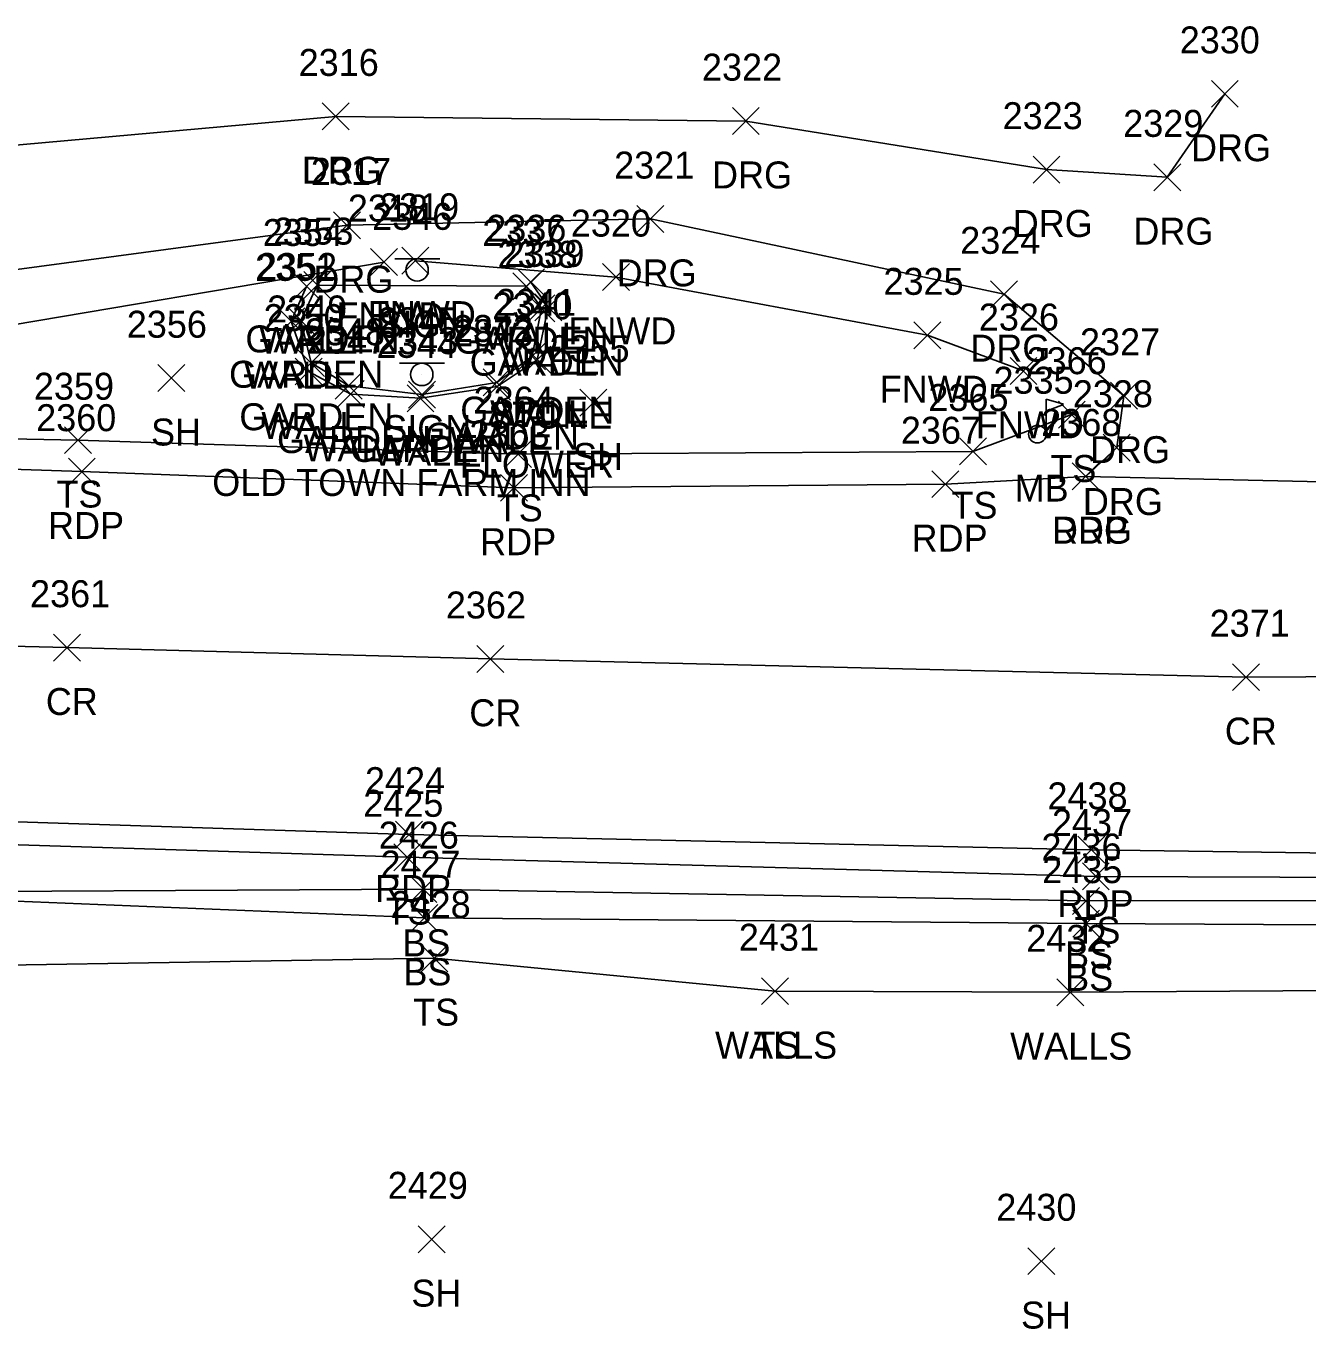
# Model space of a CAD drawing. Extents: x 1611797 to 1633212, y 298978 to 305475.
# Drawn here: x 1615253.5 to 1615348.7, y 301457.7 to 301554.4 of the extents above; entities that cross this region are included whole.
import ezdxf

# ---------------------------------------------------------------- set-up
doc = ezdxf.new("R2010")
doc.units = 0
for name, color, linetype in [('L_A', 7, 'Continuous'), ('L_C', 7, 'Continuous'), ('L_I', 7, 'Continuous'), ('L_TIC', 7, 'Continuous'), ('LAPB', 7, 'Continuous'), ('LELB', 7, 'Continuous'), ('LFNC', 7, 'Continuous'), ('LMB', 7, 'Continuous'), ('LW', 7, 'Continuous'), ('LWS', 7, 'Continuous'), ('P_A', 7, 'Continuous'), ('P_I', 7, 'Continuous'), ('P_TIC', 7, 'Continuous'), ('PET', 7, 'Continuous'), ('PRC', 7, 'Continuous'), ('R_A', 7, 'Continuous'), ('R_I', 7, 'Continuous'), ('R_TIC', 7, 'Continuous'), ('RDG', 7, 'Continuous'), ('S_A', 7, 'Continuous'), ('S_C', 7, 'Continuous'), ('S_I', 7, 'Continuous'), ('SSGN', 7, 'Continuous')]:
    doc.layers.add(name, color=color, linetype=linetype)

msp = doc.modelspace()

# ---------------------------------------------------------------- linework, layer by layer
at = {"layer": 'L_TIC'}
for points in [[(1615279.11, 301535.848), (1615281.11, 301537.848)], [(1615281.11, 301535.848), (1615279.11, 301537.848)], [(1615281.438, 301535.946), (1615283.438, 301537.946)], [(1615283.438, 301535.946), (1615281.438, 301537.946)], [(1615290.01, 301534.353), (1615292.01, 301536.353)], [(1615292.01, 301534.353), (1615290.01, 301536.353)], [(1615296.319, 301534.735), (1615298.319, 301536.735)], [(1615298.319, 301534.735), (1615296.319, 301536.735)], [(1615273.359, 301534.038), (1615275.359, 301536.038)], [(1615275.359, 301534.038), (1615273.359, 301536.038)], [(1615274.144, 301534.142), (1615276.144, 301536.142)], [(1615276.144, 301534.142), (1615274.144, 301536.142)], [(1615274.144, 301534.142), (1615276.144, 301536.142)], [(1615276.144, 301534.142), (1615274.144, 301536.142)], [(1615289.662, 301534.047), (1615291.662, 301536.047)], [(1615291.662, 301534.047), (1615289.662, 301536.047)], [(1615289.662, 301534.047), (1615291.662, 301536.047)], [(1615291.662, 301534.047), (1615289.662, 301536.047)], [(1615290.791, 301532.419), (1615292.791, 301534.419)], [(1615292.791, 301532.419), (1615290.791, 301534.419)], [(1615291.301, 301532.49), (1615293.301, 301534.49)], [(1615293.301, 301532.49), (1615291.301, 301534.49)], [(1615272.222, 301531.452), (1615274.222, 301533.452)], [(1615274.222, 301531.452), (1615272.222, 301533.452)], [(1615272.93, 301531.52), (1615274.93, 301533.52)], [(1615274.93, 301531.52), (1615272.93, 301533.52)], [(1615319.445, 301530.414), (1615321.445, 301532.414)], [(1615321.445, 301530.414), (1615319.445, 301532.414)], [(1615290.099, 301528.856), (1615292.099, 301530.856)], [(1615292.099, 301528.856), (1615290.099, 301530.856)], [(1615290.486, 301528.594), (1615292.486, 301530.594)], [(1615292.486, 301528.594), (1615290.486, 301530.594)], [(1615273.506, 301527.724), (1615275.506, 301529.724)], [(1615275.506, 301527.724), (1615273.506, 301529.724)], [(1615273.692, 301528.365), (1615275.692, 301530.365)], [(1615275.692, 301528.365), (1615273.692, 301530.365)], [(1615326.581, 301527.766), (1615328.581, 301529.766)], [(1615328.581, 301527.766), (1615326.581, 301529.766)], [(1615263.321, 301527.232), (1615265.321, 301529.232)], [(1615265.321, 301527.232), (1615263.321, 301529.232)], [(1615276.49, 301526.669), (1615278.49, 301528.669)], [(1615278.49, 301526.669), (1615276.49, 301528.669)], [(1615287.477, 301526.919), (1615289.477, 301528.919)], [(1615289.477, 301526.919), (1615287.477, 301528.919)], [(1615287.5, 301526.6), (1615289.5, 301528.6)], [(1615289.5, 301526.6), (1615287.5, 301528.6)], [(1615276.636, 301526.049), (1615278.636, 301528.049)], [(1615278.636, 301526.049), (1615276.636, 301528.049)], [(1615281.815, 301525.738), (1615283.815, 301527.738)], [(1615283.815, 301525.738), (1615281.815, 301527.738)], [(1615281.919, 301526.012), (1615283.919, 301528.012)], [(1615283.919, 301526.012), (1615281.919, 301528.012)], [(1615294.644, 301525.418), (1615296.644, 301527.418)], [(1615296.644, 301525.418), (1615294.644, 301527.418)], [(1615330.171, 301524.525), (1615332.171, 301526.525)], [(1615332.171, 301524.525), (1615330.171, 301526.525)], [(1615256.378, 301522.63), (1615258.378, 301524.63)], [(1615258.378, 301522.63), (1615256.378, 301524.63)], [(1615322.825, 301521.795), (1615324.825, 301523.795)], [(1615324.825, 301521.795), (1615322.825, 301523.795)], [(1615289.065, 301521.601), (1615291.065, 301523.601)], [(1615291.065, 301521.601), (1615289.065, 301523.601)], [(1615280.823, 301491.679), (1615282.823, 301493.679)], [(1615282.823, 301491.679), (1615280.823, 301493.679)], [(1615331.953, 301490.253), (1615333.953, 301492.253)], [(1615333.953, 301490.253), (1615331.953, 301492.253)], [(1615282.024, 301489.319), (1615284.024, 301491.319)], [(1615284.024, 301489.319), (1615282.024, 301491.319)], [(1615331.229, 301488.433), (1615333.229, 301490.433)], [(1615333.229, 301488.433), (1615331.229, 301490.433)], [(1615282.104, 301487.171), (1615284.104, 301489.171)], [(1615284.104, 301487.171), (1615282.104, 301489.171)], [(1615331.233, 301486.755), (1615333.233, 301488.755)], [(1615333.233, 301486.755), (1615331.233, 301488.755)], [(1615282.851, 301484.18), (1615284.851, 301486.18)], [(1615284.851, 301484.18), (1615282.851, 301486.18)], [(1615308.139, 301481.738), (1615310.139, 301483.738)], [(1615310.139, 301481.738), (1615308.139, 301483.738)], [(1615308.139, 301481.738), (1615310.139, 301483.738)], [(1615310.139, 301481.738), (1615308.139, 301483.738)], [(1615330.05, 301481.658), (1615332.05, 301483.658)], [(1615332.05, 301481.658), (1615330.05, 301483.658)], [(1615282.648, 301463.33), (1615284.648, 301465.33)], [(1615284.648, 301463.33), (1615282.648, 301465.33)], [(1615327.909, 301461.7), (1615329.909, 301463.7)], [(1615329.909, 301461.7), (1615327.909, 301463.7)]]:
    msp.add_lwpolyline(points, dxfattribs=at)
at = {"layer": 'LAPB'}
for points in [[(1615290.662, 301535.047), (1615291.791, 301533.419), (1615291.099, 301529.856), (1615288.477, 301527.919), (1615282.919, 301527.012), (1615277.49, 301527.669), (1615274.692, 301529.365), (1615273.93, 301532.52), (1615275.144, 301535.142)], [(1615290.662, 301535.047), (1615275.144, 301535.142)]]:
    msp.add_lwpolyline(points, dxfattribs=at)
at = {"layer": 'LELB'}
for points in [[(1615230.11, 301524.922), (1615238.425, 301524.007), (1615257.378, 301523.63), (1615290.065, 301522.601), (1615323.825, 301522.795), (1615331.171, 301525.525)], [(1615135.071, 301495.761), (1615182.71, 301493.095), (1615200.62, 301491.369), (1615237.017, 301490.049), (1615283.024, 301490.319), (1615332.229, 301489.433), (1615367.288, 301489.489), (1615415.165, 301489.476), (1615461.146, 301487.512), (1615489.04, 301481.907), (1615489.776, 301481.977), (1615494.762, 301481.706), (1615499.219, 301481.59), (1615505.435, 301481.232), (1615512.849, 301484.982), (1615523.287, 301488.148), (1615565.537, 301489.63)], [(1615179.356, 301495.542), (1615238.13, 301494.061), (1615281.823, 301492.679), (1615332.953, 301491.253), (1615367.08, 301491.116), (1615415.17, 301490.398), (1615463.455, 301489.366), (1615485.767, 301488.198), (1615488.262, 301485.173)], [(1615134.448, 301474.569), (1615137.467, 301487.518), (1615142.682, 301492.896), (1615182.793, 301490.04), (1615200.101, 301488.135), (1615232.281, 301484.351), (1615283.851, 301485.18), (1615309.139, 301482.738)], [(1615237.017, 301490.049), (1615283.104, 301488.171), (1615332.233, 301487.755), (1615367.345, 301487.55), (1615415.322, 301486.919), (1615460.207, 301484.871), (1615489.369, 301480.08), (1615494.635, 301473.717)]]:
    msp.add_lwpolyline(points, dxfattribs=at)
at = {"layer": 'LFNC'}
for points in [[(1615233.571, 301526.811), (1615248.741, 301531.535), (1615280.11, 301536.848)], [(1615282.438, 301536.946), (1615297.319, 301535.735), (1615320.445, 301531.414), (1615327.581, 301528.766)]]:
    msp.add_lwpolyline(points, dxfattribs=at)
at = {"layer": 'LMB'}
for p, q in [((1615329.261, 301526.676), (1615330.555, 301526.294)), ((1615329.268, 301524.083), (1615329.266, 301526.678)), ((1615329.266, 301525.776), (1615330.549, 301526.285)), ((1615328.612, 301524.075), (1615328.612, 301524.075))]:
    msp.add_line(p, q, dxfattribs=at)
msp.add_circle((1615328.611, 301524.075), 0.656, dxfattribs=at)
at = {"layer": 'LW'}
msp.add_lwpolyline([(1615291.01, 301535.353), (1615292.301, 301533.49), (1615291.486, 301529.594), (1615288.5, 301527.6), (1615282.815, 301526.738), (1615277.636, 301527.049), (1615274.506, 301528.724), (1615273.222, 301532.452), (1615274.359, 301535.038)], dxfattribs=at)
at = {"layer": 'LWS'}
msp.add_lwpolyline([(1615309.139, 301482.738), (1615331.05, 301482.658), (1615358.695, 301482.848), (1615417.126, 301482.013), (1615442.972, 301482.142), (1615457.095, 301482.675), (1615467.781, 301481.999)], dxfattribs=at)
at = {"layer": 'P_TIC'}
for points in [[(1615256.671, 301520.297), (1615258.671, 301522.297)], [(1615258.671, 301520.297), (1615256.671, 301522.297)], [(1615331.204, 301519.943), (1615333.204, 301521.943)], [(1615333.204, 301519.943), (1615331.204, 301521.943)], [(1615288.753, 301519.093), (1615290.753, 301521.093)], [(1615290.753, 301519.093), (1615288.753, 301521.093)], [(1615320.783, 301519.363), (1615322.783, 301521.363)], [(1615322.783, 301519.363), (1615320.783, 301521.363)], [(1615255.563, 301507.234), (1615257.563, 301509.234)], [(1615257.563, 301507.234), (1615255.563, 301509.234)], [(1615287.003, 301506.397), (1615289.003, 301508.397)], [(1615289.003, 301506.397), (1615287.003, 301508.397)], [(1615343.096, 301505.041), (1615345.096, 301507.041)], [(1615345.096, 301505.041), (1615343.096, 301507.041)], [(1615280.951, 301493.361), (1615282.951, 301495.361)], [(1615282.951, 301493.361), (1615280.951, 301495.361)], [(1615331.62, 301492.231), (1615333.62, 301494.231)], [(1615333.62, 301492.231), (1615331.62, 301494.231)]]:
    msp.add_lwpolyline(points, dxfattribs=at)
at = {"layer": 'PET'}
for points in [[(1615142.946, 301524.074), (1615174.411, 301524.044), (1615178.387, 301526.37), (1615201.604, 301526.436), (1615223.594, 301525.799), (1615232.103, 301522.147), (1615257.671, 301521.297), (1615289.753, 301520.093), (1615321.783, 301520.363), (1615332.204, 301520.943), (1615362.893, 301520.238), (1615366.82, 301519.177), (1615392.251, 301518.728), (1615435.41, 301518.321), (1615495.64, 301517.787), (1615533.402, 301517.836), (1615565.945, 301517.336)], [(1615136.457, 301498.095), (1615183.514, 301496.737), (1615238.286, 301495.772), (1615281.951, 301494.361), (1615332.62, 301493.231), (1615366.847, 301492.766), (1615415.142, 301492.226), (1615463.728, 301491.907), (1615523.213, 301491.769), (1615565.652, 301491.507), (1615604.418, 301491.288), (1615650.576, 301491.377), (1615696.82, 301491.212), (1615742.604, 301491.137), (1615790.502, 301490.828), (1615833.333, 301490.511), (1615872.315, 301490.361), (1615916.91, 301490.766), (1615952.964, 301490.824), (1615957.121, 301489.367), (1615991.141, 301489.805)]]:
    msp.add_lwpolyline(points, dxfattribs=at)
at = {"layer": 'PRC'}
msp.add_lwpolyline([(1615142.895, 301510.745), (1615196.64, 301509.677), (1615256.563, 301508.234), (1615288.003, 301507.397), (1615344.096, 301506.041), (1615366.393, 301506.163), (1615392.516, 301505.723), (1615432.008, 301505.199), (1615494.472, 301504.952), (1615533.598, 301504.748), (1615565.585, 301504.325), (1615604.181, 301504.079), (1615650.059, 301504.113), (1615697.506, 301503.8), (1615741.702, 301503.326), (1615791.714, 301502.936), (1615833.167, 301502.789), (1615874.42, 301502.642), (1615915.553, 301503.017), (1616010.706, 301505.129)], dxfattribs=at)
at = {"layer": 'R_TIC'}
for points in [[(1615341.529, 301548.33), (1615343.529, 301550.33)], [(1615343.529, 301548.33), (1615341.529, 301550.33)], [(1615275.517, 301546.66), (1615277.517, 301548.66)], [(1615277.517, 301546.66), (1615275.517, 301548.66)], [(1615305.969, 301546.31), (1615307.969, 301548.31)], [(1615307.969, 301546.31), (1615305.969, 301548.31)], [(1615328.292, 301542.709), (1615330.292, 301544.709)], [(1615330.292, 301542.709), (1615328.292, 301544.709)], [(1615337.252, 301542.137), (1615339.252, 301544.137)], [(1615339.252, 301542.137), (1615337.252, 301544.137)], [(1615298.883, 301539.043), (1615300.883, 301541.043)], [(1615300.883, 301539.043), (1615298.883, 301541.043)], [(1615276.365, 301538.573), (1615278.365, 301540.573)], [(1615278.365, 301538.573), (1615276.365, 301540.573)], [(1615325.142, 301533.458), (1615327.142, 301535.458)], [(1615327.142, 301533.458), (1615325.142, 301535.458)], [(1615334.036, 301525.924), (1615336.036, 301527.924)], [(1615336.036, 301525.924), (1615334.036, 301527.924)], [(1615333.502, 301522.074), (1615335.502, 301524.074)], [(1615335.502, 301522.074), (1615333.502, 301524.074)], [(1615331.204, 301519.943), (1615333.204, 301521.943)], [(1615333.204, 301519.943), (1615331.204, 301521.943)]]:
    msp.add_lwpolyline(points, dxfattribs=at)
at = {"layer": 'RDG'}
for points in [[(1615225.348, 301550.196), (1615232.765, 301544.839), (1615249.69, 301545.258), (1615276.517, 301547.66), (1615306.969, 301547.31), (1615329.292, 301543.709), (1615338.252, 301543.137), (1615342.529, 301549.33)], [(1615223.594, 301525.799), (1615227.571, 301529.431), (1615234.29, 301532.371), (1615248.754, 301535.742), (1615277.365, 301539.573), (1615299.883, 301540.043), (1615326.142, 301534.458), (1615335.036, 301526.924), (1615334.502, 301523.074), (1615332.204, 301520.943)]]:
    msp.add_lwpolyline(points, dxfattribs=at)
at = {"layer": 'SSGN'}
for p, q in [((1615280.913, 301537.091), (1615284.246, 301537.091)), ((1615282.56, 301536.258), (1615282.56, 301536.258)), ((1615281.26, 301529.341), (1615284.593, 301529.341)), ((1615282.907, 301528.508), (1615282.907, 301528.508))]:
    msp.add_line(p, q, dxfattribs=at)
for centre in [(1615282.56, 301536.258), (1615282.907, 301528.508)]:
    msp.add_circle(centre, 0.833, dxfattribs=at)

# ---------------------------------------------------------------- texts
at = {"layer": 'L_A'}
for s, p in [('FNWD', (1615276.575, 301531.848)), ('FNWD', (1615278.903, 301531.946)), ('WALL', (1615287.499, 301530.353)), ('FNWD', (1615293.784, 301530.735)), ('GARDEN', (1615269.814, 301530.142)), ('GARDEN', (1615269.814, 301530.142)), ('WALL', (1615270.847, 301530.038)), ('GARDEN', (1615285.332, 301530.047)), ('GARDEN', (1615285.332, 301530.047)), ('GARDEN', (1615286.461, 301528.419)), ('WALL', (1615288.79, 301528.49)), ('GARDEN', (1615268.6, 301527.52)), ('WALL', (1615269.71, 301527.452)), ('FNWD', (1615316.909, 301526.414)), ('GARDEN', (1615285.768, 301524.856)), ('WALL', (1615287.974, 301524.594)), ('GARDEN', (1615269.361, 301524.365)), ('WALL', (1615270.994, 301523.724)), ('FNWD', (1615324.046, 301523.766)), ('SH', (1615262.809, 301523.232)), ('GARDEN', (1615272.159, 301522.669)), ('GARDEN', (1615283.146, 301522.919)), ('WALL', (1615284.988, 301522.6)), ('WALL', (1615274.124, 301522.049)), ('GARDEN', (1615277.589, 301522.012)), ('WALL', (1615279.303, 301521.738)), ('SH', (1615294.132, 301521.418)), ('TS', (1615329.58, 301520.525)), ('MB', (1615326.919, 301519.075)), ('TS', (1615255.787, 301518.63)), ('TS', (1615322.234, 301517.795)), ('TS', (1615288.475, 301517.601)), ('TS', (1615280.232, 301487.679)), ('TS', (1615331.362, 301486.253)), ('BS', (1615281.465, 301485.319)), ('BS', (1615330.67, 301484.433)), ('BS', (1615281.545, 301483.171)), ('BS', (1615330.674, 301482.755)), ('TS', (1615282.26, 301480.18)), ('WALLS', (1615304.682, 301477.738)), ('TS', (1615307.548, 301477.738)), ('WALLS', (1615326.593, 301477.658)), ('SH', (1615282.136, 301459.33)), ('SH', (1615327.397, 301457.7))]:
    msp.add_text(s, height=2, dxfattribs=at).set_placement(p)
at = {"layer": 'L_C'}
for s, p in [('STONE', (1615287.845, 301524.49)), ('FLOWER', (1615285.737, 301520.856))]:
    msp.add_text(s, height=2, dxfattribs=at).set_placement(p)
at = {"layer": 'L_I'}
for s, p in [('2318', (1615277.418, 301539.848)), ('2319', (1615279.737, 301539.946)), ('2353', (1615271.885, 301538.142)), ('2353', (1615271.885, 301538.142)), ('2337', (1615287.403, 301538.047)), ('2337', (1615287.403, 301538.047)), ('2336', (1615287.695, 301538.353)), ('2320', (1615293.973, 301538.735)), ('2354', (1615271.099, 301538.038)), ('2338', (1615288.532, 301536.419)), ('2339', (1615289.034, 301536.49)), ('2351', (1615270.529, 301535.452)), ('2352', (1615270.671, 301535.52)), ('2325', (1615317.185, 301534.414)), ('2349', (1615271.424, 301532.365)), ('2340', (1615288.14, 301532.594)), ('2341', (1615288.406, 301532.856)), ('2350', (1615271.16, 301531.724)), ('2326', (1615324.266, 301531.766)), ('2356', (1615261.006, 301531.232)), ('2348', (1615274.23, 301530.669)), ('2342', (1615285.217, 301530.919)), ('2873', (1615285.24, 301530.6)), ('2347', (1615274.376, 301530.049)), ('2344', (1615279.555, 301529.738)), ('2343', (1615279.659, 301530.012)), ('2355', (1615292.385, 301529.418)), ('2366', (1615327.809, 301528.525)), ('2359', (1615254.11, 301526.63)), ('2335', (1615325.352, 301527.075)), ('2364', (1615286.758, 301525.601)), ('2365', (1615320.518, 301525.795)), ('2425', (1615278.563, 301495.679)), ('2437', (1615329.693, 301494.253)), ('2426', (1615279.71, 301493.319)), ('2436', (1615328.914, 301492.433)), ('2427', (1615279.844, 301491.171)), ('2435', (1615328.973, 301490.755)), ('2428', (1615280.591, 301488.18)), ('2431', (1615306.446, 301485.738)), ('2431', (1615306.446, 301485.738)), ('2432', (1615327.79, 301485.658)), ('2429', (1615280.381, 301467.33)), ('2430', (1615325.563, 301465.7))]:
    msp.add_text(s, height=2, dxfattribs=at).set_placement(p)
at = {"layer": 'P_A'}
for s, p in [('RDP', (1615255.159, 301516.297)), ('RDP', (1615329.692, 301515.943)), ('RDP', (1615287.241, 301515.093)), ('RDP', (1615319.271, 301515.363)), ('CR', (1615254.996, 301503.234)), ('CR', (1615286.436, 301502.397)), ('CR', (1615342.529, 301501.041)), ('RDP', (1615279.439, 301489.361)), ('RDP', (1615330.108, 301488.231))]:
    msp.add_text(s, height=2, dxfattribs=at).set_placement(p)
at = {"layer": 'P_I'}
for s, p in [('2360', (1615254.277, 301524.297)), ('2368', (1615328.897, 301523.943)), ('2363', (1615286.446, 301523.093)), ('2367', (1615318.476, 301523.363)), ('2361', (1615253.823, 301511.234)), ('2362', (1615284.696, 301510.397)), ('2371', (1615341.403, 301509.041)), ('2424', (1615278.691, 301497.361)), ('2438', (1615329.36, 301496.231))]:
    msp.add_text(s, height=2, dxfattribs=at).set_placement(p)
at = {"layer": 'R_A'}
for p in [(1615340.017, 301544.33), (1615274.005, 301542.66), (1615304.458, 301542.31), (1615326.78, 301538.709), (1615335.74, 301538.137), (1615274.854, 301534.573), (1615297.371, 301535.043), (1615323.631, 301529.458), (1615332.524, 301521.924), (1615331.99, 301518.074), (1615329.692, 301515.943)]:
    msp.add_text('DRG', height=2, dxfattribs=at).set_placement(p)
at = {"layer": 'R_I'}
for s, p in [('2330', (1615339.182, 301552.33)), ('2316', (1615273.769, 301550.66)), ('2322', (1615303.71, 301550.31)), ('2323', (1615326.032, 301546.709)), ('2329', (1615334.984, 301546.137)), ('2321', (1615297.191, 301543.043)), ('2317', (1615274.673, 301542.573)), ('2324', (1615322.883, 301537.458)), ('2327', (1615331.776, 301529.924)), ('2328', (1615331.242, 301526.074)), ('2368', (1615328.897, 301523.943))]:
    msp.add_text(s, height=2, dxfattribs=at).set_placement(p)
at = {"layer": 'S_A'}
for p in [(1615279.698, 301531.237), (1615280.045, 301523.488)]:
    msp.add_text('SIGN', height=2, dxfattribs=at).set_placement(p)
at = {"layer": 'S_C'}
msp.add_text('OLD TOWN FARM INN', height=2, dxfattribs=at).set_placement((1615267.352, 301519.488))
at = {"layer": 'S_I'}
for s, p in [('2346', (1615279.225, 301539.237)), ('2345', (1615279.628, 301531.488))]:
    msp.add_text(s, height=2, dxfattribs=at).set_placement(p)

doc.saveas('drawing.dxf')
